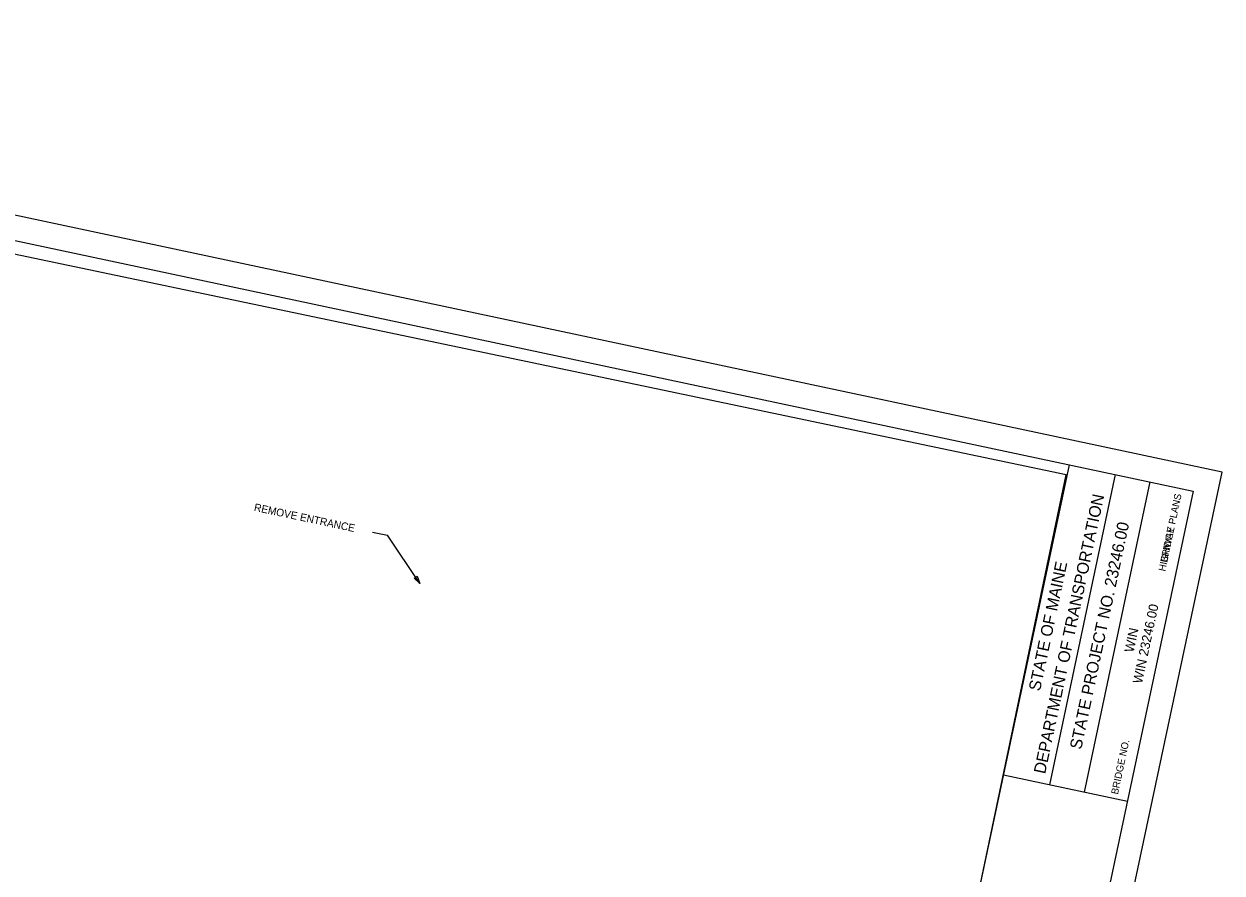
# Model space of a CAD drawing. Extents: x 1161043 to 1161989, y 610342 to 611057.
# Drawn here: x 1161516.3 to 1161989.2, y 610722.2 to 611057 of the extents above; entities that cross this region are included whole.
import ezdxf

# ---------------------------------------------------------------- set-up
doc = ezdxf.new("R2010")
doc.units = 0
for name, color, linetype in [('ANNOTATION', 7, 'Continuous'), ('BORDER', 7, 'Continuous'), ('BRIDGE_TITLE', 7, 'Continuous'), ('CLIPS', 7, 'Continuous'), ('HIGHWAY_TITLE', 7, 'Continuous'), ('PLOT BOUNDARY', 7, 'Continuous')]:
    doc.layers.add(name, color=color, linetype=linetype)

msp = doc.modelspace()

# ---------------------------------------------------------------- linework, layer by layer
at = {"layer": 'ANNOTATION'}
for p in [(1161653.89, 610856.62), (1161672.6, 610836.39)]:
    msp.add_line(p, (1161659.75, 610855.38), dxfattribs=at)
msp.add_lwpolyline([(1161671.54, 610839.3), (1161672.6, 610836.39), (1161670.29, 610838.46)], close=True, dxfattribs=at)
at = {"layer": 'BORDER'}
for p, q in [((1161819.77, 610369.67), (1161928.93, 610883.2)), ((1161921.17, 610757.04), (1161947.16, 610879.31)), ((1161934.84, 610754.14), (1161960.83, 610876.41)), ((1161902.94, 610760.9), (1161951.84, 610750.51))]:
    msp.add_line(p, q, dxfattribs=at)
msp.add_lwpolyline([(1161195.32, 611039.14), (1161977.83, 610872.81), (1161868.68, 610359.28), (1161086.16, 610525.61)], close=True, dxfattribs=at)
at = {"layer": 'CLIPS'}
msp.add_lwpolyline([(1161142.37, 610788.34), (1161876.39, 610634.52), (1161927.67, 610879.21), (1161193.65, 611033.03)], close=True, dxfattribs=at)
at = {"layer": 'PLOT BOUNDARY'}
msp.add_lwpolyline([(1161043.4, 610519.06), (1161874.82, 610342.33), (1161989.18, 610880.32), (1161157.75, 611057.04)], close=True, dxfattribs=at)

# ---------------------------------------------------------------- texts
at = {"layer": 'ANNOTATION'}
msp.add_text('REMOVE ENTRANCE', height=3, rotation=348, dxfattribs=at).set_placement((1161606.9, 610865.08))
at = {"layer": 'BORDER'}
for s, height, p in [('DEPARTMENT OF TRANSPORTATION', 4.6588, (1161919.35, 610761.05)), ('STATE PROJECT NO. 23246.00', 4.6588, (1161933.59, 610770.68)), ('STATE OF MAINE', 4.6588, (1161917.34, 610793.71)), ('WIN 23246.00', 3.7264, (1161957.54, 610796.67)), ('WIN', 3.726, (1161954.23, 610808.97))]:
    msp.add_text(s, height=height, rotation=78, dxfattribs=at).set_placement(p)
at = {"layer": 'BRIDGE_TITLE'}
for s, p in [('BRIDGE PLANS', (1161967.5, 610844.46)), ('BRIDGE NO.', (1161948.07, 610753.03))]:
    msp.add_text(s, height=2.795, rotation=78, dxfattribs=at).set_placement(p)
at = {"layer": 'HIGHWAY_TITLE'}
msp.add_text('HIGHWAY PLANS', height=2.795, rotation=78, dxfattribs=at).set_placement((1161966.77, 610840.99))

doc.saveas('drawing.dxf')
